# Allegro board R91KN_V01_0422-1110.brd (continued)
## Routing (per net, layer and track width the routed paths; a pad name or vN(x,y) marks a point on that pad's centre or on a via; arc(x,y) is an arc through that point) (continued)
M_MDA4: length 64.3
  TOP w0.099: U1.G29 97.72,49.4 97.48,49.65 97.48,49.8 97.6,49.92 97.78,49.92 97.9,49.8 98.03,49.8 98.15,49.67 98.15,49.33 97.91,49.09 97.91,48.89 98.06,48.73 98.06,48.45 98.04,48.42 98.04,47.94 98.05,47.92 98.07,47.9
  TOP w0.12: 98.07,47.9 98.2,47.77 98.2,47.09 98.97,46.32 98.97,45.78 99.52,45.24 v1(99.52,45.23) ; U202.F7 134.16,41.03 134.03,41.16 133.87,41.16 133.72,41.02 133.72,40.67 133.51,40.46 133.43,40.46 133.39,40.42 133.27,40.42 132.94,40.09 132.94,39.89 132.62,39.57 131.1,39.57 130.78,39.26 130.12,39.26 129.79,39.59 127.69,39.59 126.75,40.53 126.54,40.53 126.44,40.63 126.44,40.95 126.56,41.06 126.6,41.06 126.72,41.19 126.72,41.4 126.5,41.62 126.5,41.88 126.79,42.17 126.79,42.38 126.67,42.5 126.55,42.5 126.43,42.62 126.43,42.77 125.74,43.46 125.57,43.46 125.06,42.96 124.89,42.96 124.73,43.12 124.73,43.3 125.23,43.8 125.23,43.97 124.95,44.25 112.16,44.25 111.71,44.7 108.94,47.47 v1(108.79,47.47)
  BOTTOM w0.12: v1(108.79,47.47) 108.79,41.54 107.97,40.73 107.18,40.73 107.06,40.6 107.06,39.76 106.94,39.64 v4(106.82,39.64) 106.7,39.64 106.58,39.76 106.58,40.6 106.46,40.73 106.22,40.73 106.1,40.6 106.1,39.55 105.97,39.42 105.74,39.42 105.62,39.55 105.62,40.6 105.5,40.73 105.26,40.73 105.14,40.6 105.14,39.76 105.02,39.64 104.78,39.64 104.55,39.88 104.55,40.6 104.44,40.71 103.71,40.71 103.64,40.79 102.19,42.25 102.19,43.45 101.44,44.2 100.55,44.2 v1(99.52,45.23)
M_MDA5: length 64.1
  TOP w0.099: 98.23,48.95 98.23,48.85 98.27,48.81 98.29,48.81 98.42,48.69 98.42,48.69 98.42,48.55 98.25,48.37
  TOP w0.1: U1.F28 98.55,49.64 98.53,49.62 98.53,49.43 98.23,49.13 98.23,48.95 ; 98.42,47.88 98.23,48.07 98.23,48.34 98.25,48.35 98.25,48.37
  TOP w0.12: 98.42,47.88 98.42,47.88 98.42,47.35 99.55,46.23 99.57,46.23 100.16,45.65 v1(100.16,45.2) ; 133.37,40.81 133.29,40.88 133.06,40.88 132.93,40.76 132.93,40.59 132.81,40.46 131.23,40.46 130.91,40.78 129.96,40.78 129.81,40.64 127.4,40.64 127.2,40.84 127.2,42.55 125.11,44.64 112.32,44.64 109.03,47.93 v1(108.16,47.93)
  BOTTOM w0.12: v1(108.16,47.93) 108.38,47.71 108.38,41.68 108.1,41.4 107.86,41.4 107.73,41.52 v4(107.73,42.12) 107.73,42.49 107.61,42.62 107.27,42.62 107.14,42.49 107.14,41.31 107.14,41.3 107.02,41.19 106.78,41.19 106.66,41.31 106.66,42.49 106.53,42.62 106.31,42.62 106.18,42.49 106.18,41.31 106.18,41.3 106.06,41.19 105.82,41.19 105.7,41.31 105.7,42.49 105.57,42.62 105.34,42.62 105.22,42.49 105.22,41.31 105.22,41.3 105.1,41.19 104.86,41.19 104.74,41.31 104.74,42.49 104.62,42.62 104.38,42.62 104.26,42.5 104.26,41.31 104.14,41.19 103.85,41.19 103.72,41.31 103.72,42.48 103.6,42.61 103.38,42.61 103.25,42.48 103.25,42.17 103.12,42.05 102.94,42.05 102.62,42.36 102.62,43.7 102.09,44.24 101.7,44.24 101.34,44.6 100.68,44.6 100.21,45.07 100.21,45.15 v1(100.16,45.2)
M_MDA6: length 63.5
  TOP w0.1: U1.F32 98.57,48.2
  TOP w0.12: 133.37,42.41 133.01,42.06 131.51,42.06 131.26,42.3 131.26,42.32 130.4,43.19 127.67,43.19 125.43,45.44 112.64,45.44 109.32,48.75 106.1,48.75 106.05,48.69 v1(105.91,48.69) ; v1(100.76,45.65) 100.75,45.66 100.75,45.66 100.72,45.69 100.58,45.69 98.72,47.55 98.72,48.05 98.57,48.2
  BOTTOM w0.12: v1(105.91,48.69) 105.91,48.25 105.7,48.05 105.15,48.05 105.02,48.17 105.02,48.5 104.89,48.62 104.4,48.62 104.28,48.5 104.28,48.17 104.14,48.05 102.42,48.05 102.3,47.92 102.3,47.7 102.42,47.58 105.62,47.58 105.74,47.45 105.74,47.23 105.62,47.1 102.44,47.1 102.32,46.98 102.32,46.74 102.44,46.62 105.72,46.62 105.84,46.49 105.84,46.27 105.72,46.14 102.63,46.14 102.51,46.02 102.51,45.81 102.63,45.69 105.68,45.69 105.81,45.56 v4(105.81,45.3) 105.81,45.18 105.68,45.05 102.62,45.05 102.52,44.95 102.17,44.95 101.66,45.46 100.99,45.46 100.8,45.65 v1(100.76,45.65)
M_MDA7: length 63.8
  TOP w0.099: 98.92,48.59 98.55,48.96 U1.F30
  TOP w0.12: v1(106.44,48.34) 109.18,48.34 112.48,45.04 125.27,45.04 127.51,42.8 130.23,42.8 130.87,42.16 130.87,42.14 131.78,41.23 133.48,41.23 133.72,41.47 133.72,41.97 U202.H7 ; v1(101.53,45.02) 101.53,45.02 101.53,45.03 101.69,45.2 101.69,45.51 101.14,46.06 100.53,46.06 100.53,46.06 100.52,46.06 99.05,47.53 99.05,48.03 98.92,48.16 98.92,48.59
  BOTTOM w0.12: v1(106.44,48.34) 106.22,48.11 106.22,46.05 106.52,45.74 107.82,45.74 107.92,45.64 107.92,45.33 107.8,45.2 106.72,45.2 106.6,45.08 106.6,44.84 106.72,44.72 107.84,44.72 107.92,44.64 107.92,44.34 107.82,44.24 106.72,44.24 106.72,44.24 106.6,44.12 106.6,43.88 106.72,43.76 107.27,43.76 107.39,43.63 v4(107.39,43.4) 107.39,43.25 107.27,43.12 106.16,43.12 106.04,43.24 106.04,44.45 106.04,44.45 105.9,44.59 105.66,44.59 105.54,44.47 105.54,43.2 105.41,43.06 105.19,43.06 105.06,43.2 105.06,44.47 104.94,44.59 104.7,44.59 104.58,44.47 104.58,43.18 104.46,43.06 104.46,43.06 104.22,43.06 104.1,43.18 104.1,44.47 103.97,44.59 103.75,44.59 103.62,44.47 103.62,43.2 103.49,43.07 103.22,43.07 103.1,43.19 103.1,44.45 102.97,44.58 101.97,44.58 v1(101.53,45.02)
M_MDA8: length 66.2
  TOP w0.099: 101.58,48.28 101.41,48.28 101.07,48.62 100.93,48.62 100.92,48.63 100.8,48.63 100.58,48.84 100.58,49.05 100.45,49.17 100.28,49.17 100.15,49.05 U1.C30
  TOP w0.12: U202.A2 138.55,36.43 138.55,36.26 138.76,36.05 138.76,35.7 138.53,35.47 138.52,35.47 138.29,35.23 137.63,35.23 134.61,32.22 124.7,32.22 122.98,33.94 108.4,33.94 107.1,35.24 106.71,35.24 103.38,38.58 103.38,39.22 103.47,39.32 103.69,39.32 103.79,39.22 103.79,38.82 103.91,38.7 105.98,38.7 106.1,38.82 106.1,40.76 105.98,40.88 105.77,40.88 105.77,40.89 105.64,40.76 105.64,39.23 105.52,39.1 105.29,39.1 105.16,39.23 105.16,40.76 105.17,40.77 105.05,40.89 104.84,40.89 104.69,40.73 104.69,39.23 104.56,39.1 104.33,39.1 104.21,39.22 104.21,40.45 v4(104.09,40.57) 103.65,40.57 103.53,40.7 103.53,40.85 103.63,40.96 103.63,41.14 103.46,41.32 103.46,45.87 102.01,47.31 102.01,47.85 101.59,48.28 101.58,48.28
M_MDA9: length 67.3
  TOP w0.12: U202.C2 138.1,38.41 137.98,38.29 137.98,38.09 138.1,37.97 138.31,37.97 138.52,37.76 138.52,37.56 138.82,37.26 139.02,37.26 139.41,36.87 139.41,36.63 139.53,36.5 139.55,36.5 139.68,36.38 139.68,36.06 139.16,35.55 139.16,35.55 138.69,35.07 138.68,35.07 138.45,34.84 137.79,34.84 134.78,31.83 124.54,31.83 122.82,33.55 108.24,33.55 106.94,34.85 106.55,34.85 102.94,38.46 102.94,39.17 102.81,39.3 102.67,39.3 102.48,39.11 102.29,39.11 102.03,39.37 102.03,39.48 v4(102.14,39.59) 102.27,39.72 103.59,39.72 103.7,39.83 103.7,40.01 103.54,40.17 101.98,40.17 101.86,40.3 101.86,40.51 101.98,40.63 102.94,40.63 103.06,40.76 103.06,40.94 102.94,41.06 101.97,41.06 101.86,41.17 101.86,41.37 101.97,41.48 102.71,41.48 103.07,41.84 103.07,42.36 103.07,42.36 103.07,42.4 102.95,42.51 102.95,42.98 103.07,43.1 103.07,43.4 102.89,43.58 102.89,43.81 103.07,43.99 103.07,45.85 101.6,47.32 101.03,47.32 100.92,47.43 100.92,47.68 100.53,48.07 100.53,48.35 100.3,48.59 99.9,48.59 99.69,48.8 99.69,49.11 99.67,49.13 99.48,49.33 99.22,49.33 99.08,49.19 98.9,49.19 98.74,49.35 98.74,49.53 98.88,49.66 98.88,49.94 98.56,50.25 98.56,50.37 98.55,50.38 U1.F27
M_MDA10: length 66.1
  TOP w0.12: 137.37,36.81 137.21,36.81 137.02,36.63 137.02,36.29 137.18,36.14 137.18,35.89 134.29,33 125.03,33 123.3,34.73 115.2,34.73 114.7,35.24 114.7,36.05 114.82,36.18 114.82,38.38 114.56,38.64 114.56,38.91 113.02,40.46 110.59,40.46 109.75,41.3 108.75,41.3 107.45,40 107.45,39.05 107.65,38.85 108.5,38.85 108.67,38.67 108.67,38.48 108.55,38.35 107.55,38.35 107.45,38.25 107.45,38 107.55,37.9 108.5,37.9 108.6,37.8 108.6,37.55 108.45,37.4 107.6,37.4 107.5,37.3 107.5,37.05 107.65,36.9 108.35,36.9 108.5,36.75 108.5,36.5 108.3,36.3 107.5,36.3 107.23,36.02 107.04,36.02 106.9,36.16 v4(106.9,36.78) 106.9,40.33 106.9,41.32 106.66,41.55 106.66,41.55 106.54,41.68 104.4,41.68 104.24,41.83 104.24,46.38 103.98,46.64 103.98,46.97 102.92,48.03 102.92,48.23 101.35,49.8 U1.A28
M_MDA11: length 66.4
  TOP w0.12: 137.37,38.41 137.44,38.49 137.59,38.49 137.72,38.37 137.72,35.88 134.45,32.61 124.86,32.61 123.14,34.34 114.42,34.34 114.3,34.46 114.3,35.12 114.17,35.25 113.94,35.25 113.82,35.12 113.82,34.46 113.7,34.34 109.84,34.34 109.72,34.47 109.72,35.1 109.56,35.27 109.34,35.27 109.22,35.15 109.22,34.46 109.1,34.34 108.78,34.34 108.66,34.46 v4(108.66,34.62) 108.66,34.75 108.53,34.88 108.04,34.88 107.91,35 107.91,35.25 108.04,35.38 108.71,35.38 108.95,35.62 108.95,35.99 108.82,36.12 108.69,36.12 108.47,35.9 107.7,35.9 107.44,35.63 106.88,35.63 106.03,36.48 106.03,36.74 105.91,36.87 105.64,36.87 105.45,37.05 105.45,37.22 105.58,37.35 106.35,37.35 106.51,37.5 106.51,37.71 106.39,37.83 104.68,37.83 104.55,37.96 104.55,38.17 104.67,38.3 106.14,38.3 106.15,38.31 106.39,38.31 106.5,38.42 106.5,41.16 106.38,41.28 104.05,41.28 103.85,41.48 103.85,45.87 103.14,46.58 103.14,46.98 102.58,47.54 102.58,48.25 101.36,49.47 100.48,49.47 U1.C28
M_MDA12: length 67
  TOP w0.099: 101.33,50.68 101.09,50.92 100.81,50.92 100.78,50.88 100.56,50.88
  TOP w0.1: 100.56,50.88 100.32,50.88 100.28,50.92 100.02,50.92 99.95,50.86 99.41,50.86 99.31,50.76 99.31,50.64 U1.E27
  TOP w0.12: U202.A7 134.07,36.81 133.1,35.85 131.85,35.85 131.72,35.98 131.72,36.36 131.6,36.48 131.17,36.48 131.04,36.36 131.04,35.97 130.92,35.84 130.25,35.84 130.25,35.85 126.38,35.85 126.28,35.95 126.28,35.95 124.61,37.61 117.39,37.61 117.38,37.62 116.95,37.62 116.85,37.71 116.85,38.96 116.87,38.97 116.87,39.46 116.97,39.56 119.97,39.56 120.06,39.66 120.06,39.94 119.97,40.04 117.45,40.04 117.33,40.16 117.33,40.4 117.45,40.52 120,40.52 120.1,40.62 120.1,40.9 120,41 116.97,41 116.87,41.1 116.87,41.38 116.97,41.48 120.03,41.48 120.12,41.56 120.12,41.84 120.03,41.92 111.66,41.92 111.56,42.02 111.56,42.63 111.5,42.69 109.75,44.44 109.61,44.44 109.55,44.38 109.21,44.38 109.06,44.53 109.06,44.66 109.22,44.82 109.22,44.97 109.02,45.17 108.76,45.17 108.34,44.75 108.16,44.75 108,44.91 108,45.09 108.43,45.51 108.42,45.52 108.42,45.69 108.32,45.79 107.69,45.79 107.59,45.69 107.59,44.88 107.59,44.88 107.47,44.76 107.23,44.76 107.1,44.88 107.1,45.47 106.99,45.58 v4(106.96,45.58) 106.84,45.7 106.66,45.7 101.68,50.68 101.33,50.68
M_MDA13: length 67.9
  TOP w0.099: U1.G26 97.75,51.76 97.85,51.86 98.19,51.86 ; 98.67,51.08 98.87,51.27 98.87,51.53 ; 101.41,51.05 101.22,51.1 101.19,51.12 100.73,51.12 100.69,51.09 100.42,51.09 100.37,51.14
  TOP w0.1: 98.87,51.53 98.54,51.86 98.19,51.86 ; 100.37,51.14 99.98,51.14 99.97,51.12 99.93,51.12 99.87,51.06 99.32,51.06 99.01,50.74 98.87,50.74 98.67,50.94 98.67,51.08
  TOP w0.12: 102.98,49.8 106.53,46.24 108.5,46.24 112.4,42.34 112.41,42.34 112.42,42.34 120.41,42.34 120.52,42.24 120.52,39.48 120.2,39.17 117.36,39.17 117.26,39.06 117.26,38.81 117.25,38.8 117.25,38.1 117.34,38.01 117.59,38.01 117.71,38.13 117.71,38.66 117.83,38.78 118.07,38.78 118.19,38.66 118.19,38.13 118.31,38.01 118.55,38.01 118.67,38.13 118.67,38.66 118.79,38.78 119.03,38.78 119.15,38.66 119.15,38.13 119.27,38.01 119.51,38.01 119.63,38.13 119.63,38.66 119.75,38.78 119.99,38.78 120.11,38.66 120.11,38.13 120.23,38.01 120.47,38.01 120.59,38.13 120.59,38.95 120.69,39.05 120.97,39.05 121.02,38.99 121.02,38.99 121.07,38.95 121.07,38.13 121.19,38.01 121.46,38.01 121.56,38.11 121.56,39.25 121.69,39.38 121.93,39.38 122.05,39.26 122.05,39.22 122.05,38.11 122.15,38.01 122.43,38.01 122.53,38.11 122.53,39.22 122.53,39.26 122.65,39.38 122.89,39.38 123.01,39.26 123.01,39.22 123.01,38.1 123.11,38.01 123.43,38.01 123.53,38.1 123.53,39.28 123.63,39.38 123.97,39.38 124.11,39.24 v4(124.11,38.77) 124.11,38.08 124.16,38.02 124.69,38.02 124.77,38.09 124.77,39.17 124.88,39.29 125.12,39.29 125.22,39.19 125.22,37.68 125.32,37.58 131.28,37.58 131.38,37.48 131.38,37.33 131.53,37.18 133.26,37.18 133.35,37.27 133.35,37.38 133.37,37.4 133.37,37.62 ; 101.41,51.05 101.53,50.94 101.63,50.94
  TOP w0.13: 101.63,50.94 101.84,50.94 102.98,49.8
M_MDA14: length 67.1
  TOP w0.099: 102.16,51.55 101.92,51.79 101.47,51.79 101.37,51.7 101.36,51.69 100.73,51.69 100.71,51.71 100.42,51.71 100.39,51.69 99.85,51.69 99.75,51.59 U1.D26
  TOP w0.12: 133.37,38.41 133.37,38.52 133.26,38.62 133.02,38.62 132.92,38.52 132.92,38.27 132.91,38.27 132.91,38.09 132.79,37.97 132.41,37.97 132.21,37.77 132.21,37.5 132.1,37.4 131.78,37.4 131.68,37.5 131.68,37.57 131.44,37.8 131.44,37.8 131.28,37.98 125.73,37.98 125.63,38.08 125.63,42.06 125.53,42.16 125.32,42.16 125.22,42.06 125.22,39.77 125.13,39.69 124.86,39.69 124.77,39.77 124.77,42.03 124.65,42.15 124.41,42.15 124.29,42.03 124.29,39.87 124.21,39.78 123.9,39.78 123.81,39.87 123.81,42.03 123.69,42.15 123.45,42.15 123.33,42.03 123.33,39.9 123.21,39.77 122.94,39.77 122.85,39.87 122.85,42.03 122.73,42.15 122.49,42.15 122.37,42.03 122.37,39.9 122.25,39.77 121.97,39.77 121.89,39.85 121.89,42.03 121.77,42.15 121.53,42.15 121.41,42.03 121.41,39.8 121.27,39.66 v4(121.09,39.66) 121.05,39.66 120.92,39.78 120.92,42.15 121,42.23 121,42.63 120.89,42.74 112.56,42.74 111.85,43.45 111.84,43.45 108.66,46.65 106.75,46.65 106.74,46.65 106.6,46.65 106.31,46.94 106.31,47.22 106.09,47.44 105.8,47.44 102.16,51.08 102.16,51.55
M_MDA15: length 67.8
  TOP w0.099: U1.F25 98.55,52.39 98.65,52.49 98.94,52.49 99.03,52.39 99.03,51.65 99.22,51.46 99.37,51.46 99.47,51.56 99.47,51.78 99.57,51.88 100.31,51.88 100.34,51.91 100.79,51.91 100.82,51.89 101.1,51.89 101.13,51.91 101.34,51.97 101.35,51.97 101.37,51.99 102.14,51.99 102.55,51.58
  TOP w0.12: 102.55,51.58 102.55,51.01 105.23,48.33 105.62,48.33 105.7,48.24 105.7,47.96 105.81,47.85 106.53,47.85 106.63,47.75 106.63,47.58 106.67,47.54 106.67,47.19 106.78,47.09 107.43,47.09 107.45,47.06 107.8,47.06 107.82,47.09 108.59,47.09 108.62,47.06 108.75,47.06 108.77,47.04 108.81,47.04 112,43.85 112.5,43.85 112.6,43.74 v4(112.6,43.56) 112.6,43.33 112.79,43.13 113.12,43.13 113.24,43.25 113.24,43.79 113.31,43.85 113.58,43.85 113.7,43.74 113.7,43.23 113.8,43.13 114.08,43.13 114.18,43.23 114.18,43.74 114.3,43.85 114.54,43.85 114.66,43.74 114.66,43.23 114.76,43.13 115.04,43.13 115.14,43.23 115.14,43.74 115.26,43.85 115.5,43.85 115.62,43.74 115.62,43.23 115.72,43.13 116,43.13 116.1,43.23 116.1,43.76 116.2,43.85 116.5,43.85 116.6,43.76 116.6,43.23 116.7,43.13 116.98,43.13 117.08,43.23 117.08,43.76 117.18,43.85 117.46,43.85 117.56,43.76 117.56,43.23 117.66,43.13 117.94,43.13 118.04,43.23 118.04,43.76 118.14,43.85 118.41,43.85 118.5,43.76 118.5,43.23 118.6,43.13 118.91,43.13 119.01,43.23 119.01,43.72 119.11,43.81 119.43,43.81 119.53,43.72 119.53,43.23 119.63,43.13 119.92,43.13 120.03,43.23 120.03,43.76 120.12,43.85 120.37,43.85 120.47,43.76 120.47,43.23 120.57,43.13 120.84,43.13 120.92,43.21 120.92,43.71 121.02,43.81 121.3,43.81 121.4,43.71 121.4,42.65 121.5,42.55 121.74,42.55 121.84,42.65 121.84,43.7 121.96,43.81 122.2,43.81 122.32,43.7 122.32,42.65 122.42,42.55 122.7,42.55 122.8,42.65 122.8,43.7 122.92,43.81 123.16,43.81 123.28,43.7 123.28,42.65 123.38,42.55 123.66,42.55 123.76,42.65 123.76,43.71 123.86,43.81 124.14,43.81 124.24,43.72 124.24,43.71 124.24,42.64 124.33,42.55 125.93,42.55 126.05,42.44 126.05,40.24 126.15,40.14 126.59,40.14 126.82,39.9 126.82,39.77 126.72,39.67 126.15,39.67 126.05,39.57 126.05,39.3 126.15,39.2 127.06,39.2 127.16,39.1 127.16,38.88 127.06,38.77 126.15,38.77 126.05,38.67 126.05,38.47 126.15,38.37 131.59,38.37 131.69,38.47 131.69,38.54 131.75,38.61 131.75,38.63 131.91,38.78 132.16,38.78 132.26,38.88 132.4,38.88 132.42,38.86 132.71,38.86 132.83,38.98 133.07,38.98 133.19,38.87 133.22,38.87 133.22,38.86 133.51,38.86 133.63,38.98 134.06,38.98 134.16,39.08 134.16,39.22
M_MDA16: length 65.3
  TOP w0.099: U1.A25 101.31,52.2 101.32,52.19 102.23,52.19 102.38,52.03 102.62,51.79 102.64,51.79 102.73,51.7 102.98,51.03 104.16,50.04 104.18,50.04
  TOP w0.12: 104.18,50.04 104.18,50.03 105.91,50.03 106.22,49.72 v1(106.22,49.69)
  BOTTOM w0.12: v1(106.22,49.69) 106.72,48.77 107,48.5 108.05,48.5 108.26,48.34 108.37,48.28 108.96,47.88 109.2,47.64 109.2,42.12 110.78,40.53 112.11,40.53 112.64,40.52 115.31,38.64 124.09,29.86 v4(124.69,29.86) 135.69,29.86 141.7,35.87 141.7,40.58 140.56,42.2 140.3,42.62 140.3,42.63 140.06,42.87 139.09,42.87 139.06,42.84 138.87,42.79 U201.H8
M_MDA17: length 65.8
  TOP w0.099: 103.34,51.26 103.34,51.37 102.32,52.39 101.4,52.39 101.36,52.44 101.25,52.47 101.22,52.47 101.14,52.49 101.12,52.51 100.82,52.51 100.74,52.48 100.52,52.26 100.29,52.26 U1.C25
  TOP w0.12: v1(106.81,50.29) 106.78,50.29 106.77,50.3 104.29,50.3 104.06,50.53 104.06,50.54 103.34,51.26
  BOTTOM w0.12: 137.37,42.41 137.75,42.03 139.73,42.03 141.31,40.45 141.31,36.03 135.53,30.25 125.62,30.25 124.83,31.05 v4(124.05,31.05) 123.46,31.05 115.28,39.23 114.86,39.43 112.77,40.9 111.61,40.95 110.92,40.95 109.59,42.27 109.59,47.83 108.85,48.57 108.85,49.18 107.53,50.51 106.93,50.51 106.81,50.38 v1(106.81,50.29)
M_MDA18: length 66
  TOP w0.099: 104.01,51.15 102.56,52.6 101.48,52.6 101.37,52.71 100.71,52.71 100.68,52.69 99.94,52.69 99.81,52.56 99.81,52.33 99.69,52.2 U1.E25
  TOP w0.12: v1(108.22,50.41) 108.22,50.24 108.1,50.12 107.34,50.12 107.22,50.24 107.22,50.46 106.97,50.7 104.45,50.7 104.22,50.93 104.22,50.93 104.01,51.15
  BOTTOM w0.12: v1(108.22,50.41) 108.43,50.41 108.56,50.28 108.56,50.24 108.62,50.17 108.62,49.96 109.05,49.54 109.13,49.54 109.26,49.41 109.26,49.15 109.38,49.02 109.43,49.02 109.56,48.9 109.56,48.42 109.99,47.98 109.99,47.86 110.05,47.8 110.05,43.06 110.05,43.05 110.05,42.38 111.07,41.36 111.75,41.36 111.75,41.35 112.07,41.35 112.07,41.36 112.1,41.36 112.52,41.32 112.88,41.29 112.97,41.24 114.49,40.17 115.07,39.77 115.51,39.55 122.92,32.15 v4(123.32,32.15) 124.49,32.15 125.99,30.65 135.37,30.65 140.92,36.2 140.92,40.24 140.38,40.78 140.38,40.78 140.13,41.02 140.13,41.02 139.91,41.24 139.76,41.24 139.69,41.17 139.35,41.17 139.27,41.26 138.82,41.26 138.78,41.3 138.35,41.3 138.31,41.26 138.02,41.26 137.93,41.35 137.6,41.35 137.31,41.06 137.31,40.87 137.37,40.81
M_MDA19: length 66.2
  TOP w0.1: 102.69,53.01 102.2,53.01 101.82,53.4 101.48,53.4 101.37,53.28 100.72,53.28 100.68,53.31 99.85,53.31 99.72,53.19 99.72,53.02 U1.D24
  TOP w0.12: v1(108.97,50.41) 108.97,50.45 108.31,51.09 107.98,51.09 107.86,50.97 107.86,50.82 107.73,50.7 107.53,50.7 107.13,51.09 104.6,51.09 102.69,53.01
  BOTTOM w0.12: U201.F8 137.88,40.81 137.75,40.69 137.75,40.49 137.88,40.37 139.11,40.37 139.32,40.15 139.32,39.6 139.59,39.34 140.4,39.34 140.53,39.21 140.53,38.8 140.41,38.68 140.07,38.68 139.95,38.56 139.95,38.32 140.07,38.2 140.41,38.2 140.53,38.08 140.53,36.36 135.21,31.04 126.15,31.04 124.42,32.77 122.84,32.77 115.74,39.87 115.27,40.11 115.18,40.17 115.08,40.24 114.59,40.59 113.17,41.58 112.99,41.67 112.1,41.75 111.3,41.75 111.17,41.88 v4(111.17,42.15) 111.17,42.41 111.05,42.53 110.57,42.53 110.44,42.66 110.44,43.22 110.44,43.22 110.44,48.16 110.16,48.44 110.16,48.47 109.98,48.64 109.98,49.44 109.89,49.53 109.7,49.53 109.55,49.68 109.55,49.9 109.67,50.02 109.94,50.02 110.03,50.12 110.03,50.4 109.91,50.52 109.07,50.52 v1(108.97,50.41)
M_MDA20: length 66.5
  TOP w0.099: U1.E23 99,53.8 98.81,53.98 98.81,54.11 98.91,54.2 99.31,54.2 99.36,54.24 99.85,54.24 99.93,54.32 100.39,54.32 100.43,54.29 100.68,54.29 100.72,54.32 101.36,54.32 101.48,54.2 101.95,54.2 101.95,54.2 102.16,54.38 103.56,54.38
  TOP w0.12: 103.56,54.38 104.97,52.96 109.08,52.96 110.86,51.17 110.86,50.39 112.96,48.29 113.82,48.29 114.66,47.45 114.66,47.28 114.73,47.22 114.73,46.7 114.9,46.53 114.9,46.34 115.03,46.22 119.72,46.22 119.84,46.34 119.84,47.57 119.96,47.69 120.2,47.69 120.32,47.57 120.32,46.34 120.44,46.22 120.6,46.22 120.72,46.34 120.72,47.52 120.85,47.65 121.08,47.65 121.21,47.52 121.21,46.32 121.31,46.22 121.58,46.22 121.68,46.33 121.68,47.04 121.78,47.14 122.02,47.14 122.02,47.14 122.16,47 122.16,46.34 122.28,46.22 122.52,46.22 122.64,46.34 122.64,47.04 122.74,47.14 122.98,47.14 122.98,47.14 123.12,47 123.12,46.34 123.24,46.22 123.48,46.22 123.6,46.34 123.6,47.04 123.7,47.14 123.94,47.14 123.94,47.14 124.08,47 124.08,46.34 124.2,46.22 124.44,46.22 124.56,46.34 124.56,47.04 124.66,47.14 124.9,47.14 124.9,47.14 125.04,47 125.04,46.33 125.15,46.22 125.41,46.22 125.51,46.33 125.51,46.63 125.63,46.74 125.79,46.74 125.9,46.63 125.9,46.08 126.22,45.76 126.51,45.76 126.75,45.99 126.75,46.13 126.62,46.26 126.47,46.26 126.34,46.38 126.34,46.52 126.47,46.65 126.62,46.65 126.75,46.77 126.75,47.09 126.62,47.21 126.4,47.21 126.22,47.03 126.06,47.03 125.83,47.27 125.56,47.27 125.38,47.44 v1(125.38,47.53)
  BOTTOM w0.12: 133.37,41.62 133.07,41.62 132.69,41.23 131.79,41.23 131.56,41.48 131.56,41.54 131.43,41.66 131.33,41.66 130.85,42.14 130.69,42.14 130.56,42.02 130.56,41.84 130.44,41.72 129.9,41.72 129.82,41.64 127.49,41.64 125.93,43.2 125.93,45.84 126,45.91 126,45.95 126.41,46.37 126.41,46.38 126.66,46.62 126.66,47.27 126.53,47.4 126.25,47.4 126.25,47.4 126.03,47.4 125.91,47.52 125.91,47.65 126.03,47.77 126.19,47.77 126.29,47.88 126.29,48.1 126.19,48.2 125.12,48.2 125.01,48.1 125.01,47.8 125.29,47.53 v1(125.38,47.53)
M_MDA21: length 66.9
  TOP w0.099: 102.17,54.1 102.07,54 101.4,54 101.34,54.06 101.15,54.12 100.81,54.12 100.78,54.09 100.32,54.09 100.29,54.12 100.02,54.12 99.82,53.93 99.82,53.83
  TOP w0.1: U1.F23 98.87,53.48 99.48,53.48 99.82,53.83
  TOP w0.12: 102.17,54.1 103.52,54.1 105.06,52.56 108.92,52.56 110.47,51.01 110.47,50.23 113.06,47.64 113.8,47.64 113.81,47.63 v1(113.88,47.63)
  BOTTOM w0.12: U201.E3 134.48,40.02 134.5,40.01 134.8,40.01 134.91,39.89 134.91,39.5 134.79,39.38 134.68,39.38 134.56,39.25 134.56,38.75 134.63,38.67 134.75,38.67 134.85,38.58 134.85,36.45 134.43,36.02 134.42,36.02 133.46,35.06 128.13,35.06 v4(127.99,35.2) 127.66,35.2 127.47,35.39 127.47,35.53 127.63,35.7 127.63,35.83 127.51,35.95 127.38,35.95 127.29,35.86 127,35.86 126.87,35.99 126.87,36.14 127.01,36.28 127.01,36.45 125.42,38.04 125.25,38.04 125.12,37.91 124.95,37.91 124.78,38.08 124.78,38.25 124.91,38.38 124.91,38.55 124.74,38.72 124.57,38.72 124.44,38.59 124.27,38.59 124.1,38.76 124.1,38.93 124.23,39.06 124.23,39.23 124.06,39.4 123.89,39.4 123.76,39.27 123.6,39.27 123.43,39.44 123.43,39.61 123.55,39.74 123.55,39.91 123.38,40.08 123.21,40.08 123.09,39.95 122.92,39.95 122.75,40.12 122.75,40.29 122.88,40.42 122.88,40.59 122.71,40.76 122.54,40.76 122.41,40.63 122.24,40.63 122.07,40.8 122.07,40.97 122.2,41.1 122.2,41.27 122.03,41.44 121.86,41.44 121.73,41.31 121.56,41.31 121.39,41.48 121.39,41.65 121.52,41.78 121.52,41.95 121.35,42.12 121.18,42.12 121.05,41.99 120.88,41.99 120.71,42.16 120.71,42.33 120.84,42.46 120.84,42.63 120.67,42.8 120.5,42.8 120.37,42.67 120.2,42.67 120.03,42.84 120.03,43.01 120.16,43.14 120.16,43.31 119.99,43.48 119.82,43.48 119.69,43.35 119.52,43.35 119.35,43.52 119.35,43.69 119.48,43.81 119.48,43.98 119.19,44.27 119.19,44.59 119.19,44.6 119.19,47.94 119.07,48.06 118.87,48.06 118.75,47.94 118.75,47 118.62,46.87 118.39,46.87 118.27,47 118.27,47.94 118.27,47.95 118.15,48.06 117.94,48.06 117.81,47.95 117.81,47 117.69,46.87 117.46,46.87 117.34,47 117.34,47.94 117.34,47.95 117.34,47.95 117.22,48.06 117.05,48.06 116.92,47.94 116.92,46.99 116.8,46.87 116.6,46.87 116.47,46.99 116.47,47.94 116.35,48.06 116.18,48.06 116.06,47.94 116.06,47.02 115.93,46.9 115.77,46.9 115.64,47.02 115.64,47.59 115.58,47.66 115.57,47.66 115.23,47.66 115.23,47.66 113.9,47.66 v1(113.88,47.63)
M_MDA22: length 66.6
  TOP w0.099: 100.97,54.88 101.37,54.88 101.37,54.89 101.48,55 101.82,55 102.09,54.73
  TOP w0.1: U1.D22 100.03,54.88 100.39,54.88 100.42,54.91 100.68,54.91 100.71,54.88 100.97,54.88
  TOP w0.12: 102.09,54.73 103.68,54.73 105.05,53.35 109.24,53.35 111.26,51.33 111.26,50.56 113.13,48.69 114.16,48.69 114.53,48.32 114.53,48.31 114.75,48.09 114.88,48.09 114.88,48.08 115.08,48.08 115.18,47.98 115.18,47.97 115.18,46.8 115.32,46.66 115.54,46.66 115.66,46.79 115.66,47.94 115.8,48.08 116.02,48.08 116.15,47.95 116.15,46.74 116.27,46.62 116.5,46.62 116.63,46.74 116.63,47.95 116.75,48.08 116.94,48.08 117.07,47.95 117.07,46.74 117.19,46.62 117.42,46.62 117.55,46.74 117.55,47.95 117.67,48.08 117.99,48.08 118.12,47.95 118.12,46.74 118.24,46.62 118.43,46.62 118.56,46.74 118.56,47.95 118.68,48.08 118.88,48.08 119,47.95 119,46.78 119.12,46.66 119.32,46.66 119.44,46.78 119.44,47.95 119.57,48.08 119.78,48.08 119.8,48.09 120.37,48.09 120.38,48.08 121.78,48.08 121.79,48.07 124.53,48.07 125.03,48.56 125.03,48.75 125.15,48.88 125.37,48.88 125.49,48.75 125.49,48.53 125.61,48.41 125.77,48.41 125.88,48.53 125.88,48.75 126.01,48.88 126.18,48.88 126.31,48.75 126.31,48.34 126.18,48.22 126.09,48.22 125.81,47.94 125.22,47.94 124.97,47.7 124.97,47.68 124.85,47.55 v1(124.69,47.55)
  BOTTOM w0.12: v1(124.69,47.55) 124.5,47.55 124.27,47.33 124.27,47.13 124.4,47.01 125.98,47.01 126.11,46.88 126.11,46.62 126.02,46.53 124.35,46.53 124.23,46.41 124.23,46.16 124.39,46.01 124.57,46.01 v4(124.62,45.96) 124.66,46.01 125.44,46.01 125.54,45.91 125.54,45.68 125.41,45.55 125.03,45.55 124.91,45.43 124.91,45.23 124.94,45.21 124.94,45.07 125.03,44.97 125.41,44.97 125.54,44.84 125.54,43.04 127.1,41.48 127.1,41.16 127.62,40.64 129.81,40.64 129.96,40.78 130.31,40.78 131.03,40.06 131.84,40.06 132.15,40.37 132.62,40.37 133.07,40.81 133.37,40.81
M_MDA23: length 67.2
  TOP w0.099: 102.67,55.02 102.07,55.02 101.9,55.2 101.19,55.2 101.08,55.09 100.82,55.09 100.61,55.3 100.5,55.3
  TOP w0.1: U1.F21 98.4,55.25 98.4,55.23 98.34,55.17 98.34,55.04 98.47,54.91 98.77,54.91 98.88,55.02 98.88,55.04 99,55.16 99.13,55.16 99.22,55.09 99.26,55.09 99.44,54.9 99.6,54.9 99.62,54.91 99.78,54.91 99.94,55.09 100.28,55.09 100.5,55.3
  TOP w0.12: 102.67,55.02 103.94,55.02 105.21,53.75 109.39,53.75 111.65,51.5 111.65,50.72 113.29,49.08 114.32,49.08 114.92,48.48 122.88,48.48 123.13,48.73 123.13,48.81 123.51,49.19 123.86,49.19 123.98,49.31 123.98,49.52 123.86,49.65 123.52,49.65 123.43,49.74 123.43,50.02 123.53,50.12 123.58,50.12 123.84,50.38 124.22,50.38 124.22,50.38 124.57,50.38 124.68,50.28 125.38,50.28 125.49,50.17 125.49,49.95 125.73,49.72 125.86,49.72 125.98,49.59 125.98,49.41 125.75,49.18 125.62,49.18 125.53,49.27 124.99,49.27 124.9,49.18 124.41,49.18 124.16,48.93 124.16,48.67 124.03,48.55 123.93,48.55 v1(123.9,48.52)
  BOTTOM w0.12: U201.H3 134.16,42.1 134.04,41.98 134.01,41.98 133.8,41.77 133.8,41.47 133.97,41.3 133.97,41.13 133.8,40.97 133.8,40.74 133.43,40.37 133.22,40.37 132.92,40.07 132.92,39.87 132.62,39.57 132.23,39.57 131.91,39.26 130.05,39.26 129.72,39.59 127.72,39.59 127.21,40.09 127.21,40.49 126.71,41 126.71,41.19 125.16,42.74 125.16,42.77 124.89,43.04 124.89,43.32 125.15,43.58 125.15,44.44 125.02,44.56 124.85,44.56 124.63,44.34 124.5,44.34 124.35,44.48 124.35,44.69 124.54,44.87 124.54,45.05 124.34,45.24 124.16,45.24 123.97,45.05 123.8,45.05 123.63,45.22 123.63,45.39 123.83,45.59 123.83,45.76 123.76,45.83 123.76,46.38 v4(123.66,46.47) 123.37,46.77 123.37,46.94 123.58,47.15 123.58,47.32 123.41,47.49 123.24,47.49 123.03,47.28 122.86,47.28 122.67,47.47 122.33,47.47 122.1,47.7 122.1,47.93 122.23,48.05 123.25,48.05 123.38,48.18 123.38,48.38 123.25,48.51 122.1,48.51 121.98,48.63 121.98,48.83 122.1,48.95 123.43,48.95 123.55,49.08 123.55,49.62 123.68,49.74 124,49.74 124.13,49.62 124.13,48.65 124,48.52 v1(123.9,48.52)
M_MDA24: length 66.9
  TOP w0.099: 101.18,55.91 101.24,55.91 101.35,55.8
  TOP w0.1: 101.35,55.8 102.01,55.8 102.09,55.88 ; 101.18,55.91 101.18,55.91 101.1,55.91 101.09,55.92 100.71,55.92 100.67,55.88 100.1,55.88 99.53,55.31 99.44,55.31 U1.E21
  TOP w0.12: 102.09,55.88 104.83,55.88 105.73,54.97 109.84,54.97 112.83,51.98 112.83,51.26 v1(113.7,50.38)
  BOTTOM w0.12: v1(113.7,50.38) 110.8,50.38 110.43,50.08 110.45,49.61 110.56,48.63 110.56,48.6 110.83,48.32 110.83,43.39 112.07,42.15 113.1,42.05 113.37,41.92 113.98,41.49 114.81,40.91 115.31,40.56 115.97,40.2 120.97,35.2 123.23,33.16 124.58,33.16 126.31,31.43 135.05,31.43 140.13,36.52 140.13,37.58 139.89,37.82 139.37,37.83 139.33,37.87 139.14,37.93 138.94,37.99 U201.C8
M_MDA25: length 66.7
  TOP w0.099: 101.96,56.59 101.96,56.6 101.36,56.6 101.25,56.49 100.71,56.49 100.68,56.51 100.42,56.51 100.11,56.2 U1.D20
  TOP w0.1: 101.96,56.59 102.38,56.18 103.04,56.18
  TOP w0.12: 103.04,56.18 104.98,56.18 105.79,55.37 110,55.37 113.22,52.14 113.22,51.66 v1(114.47,50.41)
  BOTTOM w0.12: 138.16,37.62 138.16,37.86 138.29,37.98 138.48,37.98 138.61,37.86 138.61,36.2 138.76,36.05 138.76,35.71 134.88,31.82 126.48,31.82 124.75,33.55 123.38,33.55 121.24,35.48 116.42,40.3 116.21,40.51 115.62,40.83 115.5,40.9 115.49,40.92 114.16,41.84 113.57,42.25 113.21,42.44 112.76,42.48 112.19,42.59 111.23,43.55 111.23,48.48 110.95,48.76 110.95,48.99 111.07,49.12 111.92,49.12 112.05,49.24 v4(112.05,49.4) 111.92,49.52 110.97,49.52 110.84,49.65 110.84,49.85 110.97,49.98 114,49.98 114.43,50.41 v1(114.47,50.41)
M_MDA26: length 67.3
  TOP w0.099: 98.4,56.76 98.4,56.88 98.53,57 U1.F19 ; 100.63,56.87 100.8,56.7 ; 99.12,56.3 99.19,56.3 99.2,56.28 99.33,56.28 99.38,56.34 ; 99.93,56.47 100.06,56.47 100.27,56.67
  TOP w0.1: 100.8,56.7 100.81,56.69 101.09,56.69 101.2,56.8 102.14,56.8 102.49,56.45 ; 98.4,56.76 98.56,56.6 98.89,56.6 99.02,56.48 99.02,56.41 99.12,56.3 ; 100.63,56.87 100.47,56.87 100.28,56.67 100.27,56.67 ; 99.93,56.47 99.83,56.57 99.77,56.57 99.65,56.69 99.51,56.69 99.38,56.57 99.38,56.34
  TOP w0.12: v1(115.19,50.42) 115.38,50.42 115.5,50.55 115.5,50.77 115.4,50.87 114.72,50.87 114.58,51.02 v4(114.58,51.34) 114.36,51.56 114.19,51.56 114.12,51.49 113.95,51.49 113.78,51.66 113.78,51.83 113.85,51.89 113.85,52.06 110.16,55.76 105.81,55.76 105.12,56.45 102.49,56.45
  BOTTOM w0.12: 137.37,39.22 137.59,39.22 137.6,39.2 137.66,39.2 137.88,38.98 137.88,38.63 137.81,38.56 137.81,38.06 137.73,37.98 137.73,37.49 137.81,37.41 137.81,35.73 137.96,35.58 137.96,35.46 134.72,32.22 126.64,32.22 124.91,33.95 123.55,33.95 116.45,40.83 115.83,41.17 114.39,42.16 113.78,42.59 113.32,42.82 112.82,42.87 112.51,42.98 111.62,43.86 111.62,48.18 112.95,49.51 114.29,49.51 115.19,50.41 v1(115.19,50.42)
M_MDA27: length 66.3
  TOP w0.099: U1.A19 101.9,57
  TOP w0.1: 101.9,57 102.47,57 102.75,56.73
  TOP w0.12: 102.75,56.73 105.3,56.73 105.81,56.22 110.25,56.22 110.54,55.93 110.71,55.93 110.98,56.19 111.15,56.19 111.32,56.03 111.32,55.85 111.05,55.59 111.05,55.42 111.22,55.25 111.39,55.25 111.66,55.52 111.84,55.52 112,55.36 112,55.18 111.73,54.91 111.73,54.74 111.9,54.57 112.07,54.57 112.36,54.86 112.54,54.86 v4(112.7,54.7) 112.7,54.52 112.41,54.23 112.41,54.06 112.58,53.89 112.75,53.89 112.97,54.12 113.15,54.12 113.31,53.95 113.31,53.78 113.09,53.55 113.09,53.38 113.26,53.21 113.43,53.21 113.7,53.48 113.88,53.48 114.04,53.32 114.04,53.14 113.77,52.87 113.77,52.7 113.94,52.53 114.11,52.53 114.41,52.84 114.59,52.84 114.75,52.68 114.75,52.5 114.53,52.28 114.53,52.1 114.69,51.94 114.87,51.94 115.18,52.25 115.36,52.25 115.52,52.09 115.52,51.91 115.19,51.57 115.19,51.46 115.38,51.27 116,51.27 116.13,51.13 116.13,50.55 116,50.42 v1(115.91,50.42)
  BOTTOM w0.12: 137.37,36.81 137.29,36.74 137.29,35.45 137.28,35.43 137.28,35.43 134.47,32.62 134.47,32.62 134.46,32.61 126.8,32.61 125.06,34.34 123.71,34.34 123.68,34.37 116.68,41.15 116.03,41.5 114.61,42.48 113.98,42.93 113.42,43.21 112.96,43.25 112.02,44.19 112.02,48.02 113.12,49.12 114.62,49.12 115.91,50.41 v1(115.91,50.42)
M_MDA28: length 67
  TOP w0.099: 101.84,58.17 101.81,58.17 101.77,58.21 101.38,58.21 101.29,58.12 101.22,58.09 100.73,58.09 100.71,58.11 100.42,58.11 100.37,58.06 99.8,58.06 ; U1.D18 99.75,58.01
  TOP w0.1: 99.75,58.01 99.8,58.06 ; 101.84,58.17 101.88,58.13
  TOP w0.12: 105.67,57.67 105.67,57.68 112.73,57.68 113.38,57.03 113.55,57.03 114.02,57.51 114.19,57.51 114.36,57.34 114.36,57.17 113.88,56.69 113.88,56.52 114.05,56.35 114.22,56.35 114.7,56.83 114.87,56.83 115.04,56.66 115.04,56.49 114.56,56.01 114.56,55.85 114.73,55.68 114.9,55.68 115.38,56.15 115.55,56.15 115.72,55.98 115.72,55.81 115.24,55.34 115.24,55.17 115.41,55 115.58,55 116.06,55.47 116.23,55.47 116.4,55.3 116.4,55.13 115.92,54.66 115.92,54.49 116.09,54.32 116.26,54.32 116.74,54.79 116.91,54.79 117.08,54.62 117.08,54.45 116.6,53.98 116.6,53.81 116.77,53.64 116.94,53.64 117.42,54.11 117.59,54.11 117.76,53.94 117.76,53.77 117.28,53.3 117.28,53.13 117.45,52.96 117.62,52.96 118.1,53.44 118.26,53.44 118.43,53.27 118.43,53.1 117.96,52.62 117.96,52.45 118.08,52.33 118.08,52.12 117.75,51.8 117.75,51.67 117.92,51.5 117.92,51.48 118.32,51.09 118.32,50.51 118.2,50.38 v1(118.08,50.38)
  TOP w0.13: 101.88,58.13 102.33,57.67 105.67,57.67
  BOTTOM w0.12: v1(118.08,50.38) 117.6,49.91 117.6,49.35 v4(117.28,49.02) 116.99,48.73 116.99,48.56 117.09,48.46 117.89,48.46 118.02,48.58 118.02,49.15 118.14,49.27 118.41,49.27 118.54,49.15 118.54,48.58 118.66,48.46 118.94,48.46 119.06,48.58 119.06,49.06 119.19,49.19 119.46,49.19 119.59,49.06 119.59,44.44 128.57,35.45 133.29,35.45 134.3,36.46 134.3,36.46 134.31,36.46 134.52,36.67 134.52,38.06 U201.C3
M_MDA29: length 67.6
  TOP w0.099: 99.48,58.29 100.28,58.29 100.31,58.31 100.79,58.31 100.82,58.29 101.08,58.29 101.2,58.41 101.85,58.41 101.87,58.4 101.93,58.38 ; 98.84,59.03 98.67,59.03 98.55,58.91 U1.F17
  TOP w0.1: 99.48,58.29 99.35,58.16 99.35,57.94 99.24,57.83 99.07,57.83 98.95,57.94 98.95,58.91 98.84,59.03
  TOP w0.12: v1(120.54,50.4) 120.56,50.42 120.56,50.77 120.44,50.89 118.87,50.89 118.74,51.02 118.74,51.2 118.86,51.32 118.89,51.31 120.46,51.31 120.59,51.44 120.59,51.67 120.46,51.8 118.89,51.8 118.61,51.81 118.5,51.93 118.5,52.16 118.62,52.27 120.46,52.27 120.59,52.4 120.59,52.62 120.48,52.73 120.27,52.73 120.26,52.73 118.96,52.73 118.84,52.86 118.84,53.09 118.96,53.21 120.48,53.21 120.59,53.32 120.59,53.59 120.48,53.69 118.56,53.69 118.34,53.91 v4(118.34,54.06) 118.47,54.19 119.87,54.19 120,54.31 120,54.59 119.87,54.72 117.58,54.72 114.22,58.07 113.96,58.07 113.65,57.77 113.3,57.77 112.99,58.07 102.36,58.07 102.05,58.38 101.93,58.38
  BOTTOM w0.12: U201.A3 134.09,36.81 133.12,35.84 128.73,35.84 122.03,42.54 122.03,42.54 119.98,44.6 119.98,49.22 120.28,49.53 120.28,49.81 120.54,50.07 v1(120.54,50.4)
M_MDA30: length 66.4
  TOP w0.099: U1.A17 100.96,58.61 102.14,58.61
  TOP w0.12: v1(120.77,49.72) 120.98,49.93 120.98,54 120.85,54.12 120.51,54.12 120.39,54.24 120.39,54.41 120.52,54.53 120.84,54.53 120.96,54.66 120.96,55.26 120.77,55.45 120.53,55.45 120.41,55.33 120.41,55.26 v4(120.28,55.13) 119.82,55.13 119.7,55.26 119.7,56.35 119.57,56.48 119.34,56.48 119.22,56.35 119.22,55.26 119.1,55.13 118.86,55.13 118.74,55.26 118.74,56.2 118.61,56.32 118.38,56.32 118.26,56.2 118.26,55.26 118.14,55.13 117.71,55.13 117.21,55.64 117.21,55.81 118.04,56.64 118.04,56.82 117.88,56.98 117.7,56.98 116.87,56.15 116.7,56.15 116.53,56.32 116.53,56.49 117.42,57.38 117.42,57.55 117.26,57.71 117.08,57.71 116.19,56.83 116.02,56.83 115.85,57 115.85,57.17 116.79,58.1 116.79,58.28 116.62,58.44 116.45,58.44 115.51,57.51 115.34,57.51 115.17,57.68 115.17,57.85 115.49,58.17 115.49,58.34 115.37,58.47 115.11,58.47 114.83,58.19 114.66,58.19 114.39,58.46 102.62,58.46 102.61,58.47 102.29,58.47 102.14,58.61
  BOTTOM w0.12: v1(120.77,49.72) 120.67,49.62 120.67,49.37 120.67,49.36 120.67,49.09 120.38,48.79 120.38,44.76 128.71,36.42 128.84,36.42 128.96,36.55 128.96,37.06 129.08,37.19 129.34,37.19 129.47,37.06 129.47,36.37 129.59,36.24 129.82,36.24 129.95,36.37 129.95,36.56 130.07,36.69 130.71,36.69 130.83,36.56 130.83,36.37 130.96,36.24 131.76,36.24 131.89,36.37 131.89,36.44 132.21,36.76 132.21,36.96 132.42,37.17 132.5,37.17 132.59,37.26 132.71,37.26 132.75,37.3 133.18,37.3 133.35,37.12 133.35,37.05 133.37,37.03 133.37,36.81
M_MDA31: length 66.8
  TOP w0.099: U1.C17 100.5,58.6 100.82,58.91 101.08,58.91 101.16,58.83 102.43,58.83 102.45,58.86
  TOP w0.12: 102.45,58.86 117.09,58.86 117.22,58.98 117.22,59.12 118.05,59.94 119.71,59.94 119.84,59.81 119.84,59.53 119.71,59.41 118.07,59.41 117.95,59.28 117.95,59.1 118.07,58.98 119.58,58.98 119.7,58.85 119.7,58.63 119.58,58.51 117.55,58.51 117.42,58.38 v4(117.42,58.29) 117.42,58.12 117.78,57.77 118.17,57.77 118.4,58 120.09,58 120.21,57.88 120.21,57.59 120.09,57.47 118.42,57.47 118.3,57.34 118.3,57.11 118.64,56.77 119.05,56.77 119.27,56.99 120.09,56.99 120.21,56.87 120.21,55.97 120.34,55.84 120.93,55.84 121.37,55.4 121.37,50.32 121.45,50.24 v1(121.45,49.9)
  BOTTOM w0.12: v1(121.45,49.9) 121.18,49.63 121.18,48.97 120.77,48.56 120.77,44.92 127.42,38.27 127.88,38.27 128.29,37.86 128.29,37.42 128.42,37.3 128.63,37.3 128.77,37.43 128.77,37.86 128.89,37.98 129.13,37.98 129.25,37.86 129.25,37.68 129.35,37.58 129.61,37.58 129.73,37.7 129.73,37.86 129.85,37.98 130.09,37.98 130.21,37.86 130.21,37.7 130.33,37.58 130.57,37.58 130.69,37.7 130.69,37.86 130.81,37.98 131.15,37.98 131.54,37.59 132.03,37.59 132.41,37.97 133.24,37.97 133.35,38.08 133.35,38.19 133.37,38.2 133.37,38.41
M_MDA32: length 67.2
  TOP w0.099: 101.25,59.09 101.3,59.04 101.84,59.04 101.85,59.05 101.94,59.12 102.3,59.12 ; U1.E17 99.56,58.81 99.65,58.81
  TOP w0.1: 99.65,58.81 99.93,59.09 100.67,59.09 100.7,59.11 101.23,59.11 101.25,59.09
  TOP w0.12: 102.3,59.12 102.45,59.27 116.82,59.27 117.88,60.33 117.88,60.33 119.77,60.33 120.61,61.17 120.61,62.07 120.4,62.28 120.4,63 121.5,64.1 122.93,64.1 123.05,63.98 v1(123.05,63.83)
  BOTTOM w0.12: U402.D7 134.1,77.31 133.8,77.31 133.51,77.02 131.63,77.02 131.57,76.96 131.57,76.77 131.45,76.64 131.19,76.64 131.06,76.77 131.06,77.27 131.34,77.55 131.37,77.55 131.48,77.66 131.48,78.01 131.28,78.2 131.07,78.2 130.75,77.89 130.15,77.89 130.03,77.76 130.03,77.45 129.91,77.33 129.67,77.33 129.55,77.45 129.55,77.52 129.43,77.64 129.19,77.64 129.07,77.52 129.07,77.45 128.95,77.33 128.71,77.33 128.59,77.45 128.59,77.52 128.47,77.64 128.23,77.64 128.11,77.52 128.11,77.45 127.99,77.33 127.75,77.33 127.63,77.45 127.63,77.52 127.51,77.64 127.27,77.64 127.15,77.52 127.15,77.45 127.03,77.33 126.22,77.33 126.06,77.18 125.83,77.18 125.71,77.31 125.71,77.52 125.59,77.64 125.2,77.64 125.03,77.47 125.03,77.31 125.21,77.13 125.21,76.98 125.07,76.84 124.85,76.84 124.68,77.02 124.58,77.02 124.26,76.7 124.26,76.46 124.38,76.33 124.53,76.33 124.66,76.21 124.66,75.94 124.53,75.82 124.09,75.82 123.97,75.69 123.97,75.42 124.09,75.29 124.48,75.29 124.6,75.17 124.6,74.94 124.48,74.81 124.09,74.81 123.97,74.69 123.97,74.45 124.09,74.33 125.22,74.33 125.32,74.24 125.32,73.95 125.22,73.85 124.09,73.85 123.97,73.73 123.97,73.49 124.09,73.37 124.78,73.37 124.91,73.25 124.91,73.05 124.75,72.89 124.28,72.89 124.12,72.74 v4(124.12,72.63) 124.12,71.02 123.45,70.34 121.09,70.34 120.94,70.19 120.94,66.69 121.12,66.51 123.2,66.51 123.97,65.73 123.97,64.15 123.64,63.83 v1(123.05,63.83)
M_MDA33: length 66.8
  TOP w0.099: U1.D16 100.03,59.67 100.37,59.67 100.41,59.71 100.69,59.71 100.72,59.69 101.22,59.69 101.41,59.78 101.47,59.84 101.81,59.84 102.08,59.57 102.64,59.57
  TOP w0.12: v1(123.56,64.31) 123.56,64.36 123.43,64.49 123.09,64.49 123.09,64.5 121.34,64.5 121.34,64.49 121.23,64.49 121.04,64.3 121.02,64.3 119.74,63.03 119.74,62.86 120,62.59 120,62.41 119.85,62.25 119.67,62.25 119.4,62.52 119.23,62.52 119.06,62.35 119.06,62.18 119.99,61.25 119.99,61.11 119.79,60.91 119.65,60.91 118.72,61.84 118.55,61.84 118.38,61.67 118.38,61.5 118.86,61.02 118.86,60.85 118.73,60.73 118.48,60.73 118.04,61.16 117.87,61.16 116.52,59.8 116.39,59.67 102.74,59.67 102.64,59.57
  BOTTOM w0.12: 133.37,78.17 133.46,78.27 133.46,78.45 133.33,78.58 131.56,78.58 131.43,78.7 131.43,79.58 131.31,79.71 130.38,79.71 130.26,79.58 130.26,78.75 130.13,78.62 129.79,78.62 129.66,78.75 129.66,79.62 129.54,79.74 129.3,79.74 129.18,79.62 129.18,79 129.06,78.89 128.82,78.89 128.7,79 128.7,79.62 128.58,79.74 128.34,79.74 128.22,79.62 128.22,79 128.1,78.89 127.86,78.89 127.74,79 127.74,79.62 127.62,79.74 127.38,79.74 127.26,79.62 127.26,79 127.14,78.89 126.16,78.89 125.69,78.42 v4(125.69,78.42) 125.43,78.15 125.15,78.15 123.56,76.56 123.56,71 123.29,70.73 120.65,70.73 120.55,70.63 120.55,66.27 120.69,66.12 123.02,66.12 123.56,65.58 v1(123.56,64.31)
M_MDA34: length 67.6
  TOP w0.099: 102.33,59.91 102.32,59.91 102.2,60.04 101.39,60.04 101.33,59.98 101.08,59.89 100.82,59.89 100.79,59.91 100.33,59.91 100.29,59.88 98.87,59.88 U1.F15
  TOP w0.1: 102.33,59.91 103.59,59.91 103.82,60.14
  TOP w0.12: v1(123.08,64.91) 123.09,64.89 123.25,64.89 123.37,65.02 123.37,65.2 123.25,65.33 122.83,65.33 122.71,65.2 122.71,65.15 122.47,64.91 121.07,64.91 120.86,64.69 120.85,64.69 118.56,62.4 118.43,62.4 v4(117.81,61.78) 116.17,60.14 103.82,60.14
  BOTTOM w0.12: v1(123.08,64.91) 123.08,65.21 122.56,65.72 120.53,65.72 120.13,66.13 120.13,70.54 120.02,70.65 119.64,70.65 119.52,70.52 119.52,70 119.39,69.88 119.11,69.88 118.98,70 118.98,70.75 119.36,71.13 122.96,71.13 123.08,71.25 123.08,71.4 122.96,71.53 120.25,71.53 120.13,71.65 120.13,71.86 120.25,71.98 122.96,71.98 123.08,72.11 123.08,72.44 122.96,72.56 122.88,72.56 122.76,72.69 122.76,72.93 122.88,73.06 122.96,73.06 123.08,73.18 123.08,76.64 126.57,80.13 133.51,80.13 133.72,79.92 133.72,79.17 133.53,78.97 133.37,78.97
M_MDA35: length 66.4
  TOP w0.099: U1.A15 100.99,60.24 102.75,60.24 102.75,60.23
  TOP w0.12: 102.75,60.23 103.06,60.55 115.75,60.55 118.53,63.32 v4(118.69,63.32) 118.69,63.31 119.87,64.49 119.92,64.49 v1(119.98,64.55)
  BOTTOM w0.12: v1(119.98,64.55) 119.87,64.55 119.75,64.67 119.75,65.47 119.62,65.59 119.3,65.59 119.3,65.59 119.02,65.59 118.89,65.72 118.89,65.96 119.01,66.07 119.62,66.07 119.74,66.19 119.74,66.43 119.62,66.55 118.73,66.55 118.6,66.43 118.6,66.39 118.48,66.27 118.33,66.27 118.21,66.39 118.21,66.94 118.3,67.03 119.62,67.03 119.74,67.15 119.74,67.39 119.62,67.51 118.32,67.51 118.19,67.64 118.19,67.87 118.32,67.99 119.62,67.99 119.74,68.11 119.74,68.35 119.62,68.47 117.92,68.47 117.78,68.62 117.78,68.83 117.9,68.95 119.62,68.95 119.74,69.07 119.74,69.31 119.62,69.43 117.46,69.43 117.34,69.31 117.34,68.73 117.21,68.61 117,68.61 116.88,68.73 116.88,69.75 117,69.88 117.58,69.88 117.62,69.92 118.39,69.92 118.52,70.04 118.52,70.33 118.32,70.52 118.32,70.66 120.06,72.39 121.63,72.39 122.63,73.39 122.63,76.74 125.85,79.97 125.85,80.36 126.01,80.52 133.43,80.52 134.16,79.79 U402.A7
M_MDA36: length 66.9
  TOP w0.1: 102.73,61.93 102.69,61.93 102.4,61.64 101.63,61.64 101.61,61.63 101.46,61.48 100.81,61.48 100.78,61.52 100.33,61.52 100.15,61.34 100.09,61.34 U1.D14
  TOP w0.12: 102.73,61.93 104.88,61.93 105.51,62.56 109.38,62.56 111.55,64.73 111.72,64.73 111.84,64.61 111.84,63.82 111.97,63.7 112.25,63.7 112.38,63.82 112.38,65.33 112.5,65.46 112.74,65.46 112.89,65.31 112.89,63.5 113.02,63.38 113.28,63.38 113.41,63.5 113.41,65.23 113.53,65.36 113.81,65.36 113.93,65.23 113.93,64.97 113.94,64.96 113.94,62.62 114.03,62.53 114.33,62.53 114.43,62.63 114.43,65.08 v5(114.77,65.43)
  BOTTOM w0.12: v5(114.77,65.43) 115.01,65.67 115.01,67.64 114.84,67.81 114.84,68.56 115.01,68.74 115.01,69.05 114.84,69.22 114.84,69.53 115.01,69.7 115.01,70 114.84,70.18 114.84,70.48 115.01,70.66 115.01,71.05 115.73,71.77 116.81,71.77 119.64,74.6 119.64,75.04 119.65,75.05 119.65,77.77 123.01,81.13 123.01,83.19 123.36,83.54 134.25,83.54 137.34,80.44 137.34,79.8 137.37,79.78
M_MDA37: length 67.4
  TOP w0.099: U1.F13 98.97,62.11 99.22,62.11 99.33,62.11 100.53,62.12 100.73,62.31 101.29,62.31 101.36,62.24 101.85,62.24 102.29,62.68
  TOP w0.12: v1(110.97,66.22) 110.88,66.22 108.89,64.22 v4(108.89,64.15) 108.35,63.79 106.13,63.79 105.19,63.8 104.07,62.68 102.29,62.68
  BOTTOM w0.12: 137.37,78.17 137.72,77.82 138.31,77.82 138.61,78.12 138.61,78.32 138.82,78.53 139.02,78.53 140.12,79.63 140.12,80.37 139.56,80.93 139.16,80.93 135.37,84.71 122.87,84.71 121.84,83.68 121.84,81.62 119.68,79.46 117.25,79.46 117.03,79.25 115.31,77.55 115.31,76.68 115.82,76.17 115.98,76.17 115.99,76.17 117.2,76.17 117.55,75.83 118.2,75.83 118.45,75.57 118.45,75.08 116.33,72.95 114.92,72.95 114.38,72.42 114.19,72.42 113.66,71.88 113.66,68.91 v1(110.97,66.22)
M_MDA38: length 66.3
  TOP w0.099: 101,61.75 101.44,61.75 101.51,61.82
  TOP w0.1: 101,61.75 100.95,61.79 U1.A13 ; 101.51,61.82 101.53,61.84 102.31,61.84 102.64,62.16 103.63,62.16
  TOP w0.12: v1(112.47,66.22) 111.91,65.52 v4(111.72,65.3) 111.33,65.06 111.29,65.03 109.22,62.96 105.4,62.96 104.61,62.16 103.63,62.16
  BOTTOM w0.12: U402.A2 137.94,79.78 137.94,79.78 137.84,79.78 137.75,79.88 137.75,80.6 134.41,83.93 123.2,83.93 122.62,83.36 122.62,81.3 120,78.67 119.47,78.67 119.46,78.67 117.64,78.67 117.52,78.55 117.52,78.4 117.64,78.28 119.22,78.28 119.34,78.15 119.34,78.02 119.17,77.84 117.47,77.84 117.38,77.75 117.38,77.51 117.47,77.42 119.08,77.42 119.18,77.32 119.18,77.12 119.08,77.02 117.88,77.02 117.77,76.91 117.77,76.74 117.9,76.61 118.53,76.61 118.53,76.6 119.06,76.6 119.25,76.4 119.25,75.21 119.25,75.2 119.25,74.76 116.65,72.17 115.3,72.17 114.44,71.31 114.44,68.91 114.44,68.91 114.44,68.36 114.44,68.35 114.44,68.03 114.32,67.91 113.77,67.91 113.5,67.64 113.5,67.47 113.63,67.35 114.51,67.35 114.62,67.25 114.62,66.97 114.51,66.86 113.07,66.86 112.97,66.75 112.97,66.24 112.84,66.11 112.57,66.11 v1(112.47,66.22)
M_MDA39: length 66.6
  TOP w0.099: U1.C13 100.5,61.8 100.82,62.11 101.08,62.11 101.13,62.06 101.16,62.04 102.19,62.04 102.39,62.23
  TOP w0.12: v1(111.75,66.22) 110.45,64.92 v4(110.38,64.92) 110.38,64.85 108.94,63.4 105.25,63.4 104.24,62.39 102.54,62.39 102.39,62.23
  BOTTOM w0.12: U402.C2 138.16,78.39 138.52,78.74 138.52,79.1 138.7,79.28 138.7,79.49 138.52,79.67 138.52,80.08 138.16,80.44 138.16,80.73 138.09,80.8 138.09,80.97 138.21,81.1 138.21,81.27 138.05,81.44 137.87,81.44 137.75,81.31 137.58,81.31 137.41,81.48 137.41,81.65 137.49,81.73 137.49,81.89 137.31,82.07 137.15,82.07 137.07,81.99 136.9,81.99 136.73,82.16 136.73,82.33 136.81,82.41 136.81,82.57 136.63,82.75 136.47,82.75 136.39,82.67 136.22,82.67 136.05,82.84 136.05,83.01 136.13,83.09 136.13,83.25 135.95,83.43 135.79,83.43 135.71,83.35 135.54,83.35 135.37,83.52 135.37,83.69 135.45,83.77 135.45,83.93 135.27,84.11 135.11,84.11 135.03,84.03 134.87,84.03 134.57,84.32 123.03,84.32 122.23,83.52 122.23,81.46 119.84,79.07 117.42,79.07 117.32,78.97 117.31,78.97 116.77,78.42 116.77,78.22 116.82,78.17 116.99,78 116.99,77.82 116.82,77.66 116.65,77.66 116.4,77.91 116.25,77.91 116.04,77.69 116.04,77.27 115.91,77.14 115.82,77.14 115.71,77.03 115.71,76.84 115.98,76.57 116.39,76.57 116.52,76.69 116.52,77.08 116.64,77.21 116.87,77.21 117,77.08 117,76.65 117.09,76.56 117.37,76.56 117.71,76.22 118.36,76.22 118.38,76.2 118.59,76.2 118.85,75.94 118.85,75.36 118.85,75.36 118.85,74.92 116.49,72.56 115.08,72.56 114.54,72.03 114.36,72.03 114.05,71.72 114.05,68.75 112.57,67.27 112.57,66.87 112.46,66.75 112.06,66.75 111.75,66.44 v1(111.75,66.22)
M_MDA40: length 66.7
  TOP w0.099: 100.01,63.71 100.28,63.71 100.31,63.69 100.79,63.69 100.82,63.71 101.35,63.71 101.39,63.67 101.92,63.67 101.92,63.67
  TOP w0.1: 101.92,63.67 102.86,63.67 ; 100.01,63.71 99.97,63.67 99.62,63.67 U1.E11
  TOP w0.12: 102.86,63.67 103.12,63.67 104.91,65.45 107.63,65.45 112.19,70.02 121.49,70.02 121.61,69.9 121.61,68.02 121.74,67.89 122.08,67.89 122.2,68.02 122.2,69.94 122.29,70.02 122.66,70.02 122.73,69.95 122.73,69.95 122.74,69.94 122.74,67.97 122.86,67.84 123.1,67.84 123.21,67.96 123.22,67.97 123.22,69.94 123.22,69.95 123.33,70.06 123.58,70.06 123.69,69.95 123.7,69.94 123.7,67.99 123.82,67.86 124.05,67.86 124.18,67.99 124.18,69.94 124.18,69.95 124.18,70.85 124.3,70.97 124.52,70.97 124.65,70.85 124.65,67.67 124.77,67.55 125.11,67.55 125.23,67.67 125.23,70.81 125.36,70.94 125.66,70.94 125.78,70.81 125.78,69.82 125.79,67.37 v1(126.29,66.86)
  BOTTOM w0.12: v1(126.29,66.86) 126.29,66.88 125.86,67.31 125.86,67.58 125.84,67.59 125.84,71.77 126.78,72.69 127.09,72.69 127.1,72.69 130.04,72.69 v4(130.8,73.44) 131.03,73.68 132.37,73.68 132.47,73.78 132.67,73.78 133.06,74.17 133.37,74.17
M_MDA41: length 65.8
  TOP w0.099: U1.A11 100.99,63.44 102.83,63.44 102.84,63.43
  TOP w0.12: v1(125.63,66.55) 125.62,66.56 125.1,66.56 124.26,67.41 121.22,67.41 121.1,67.53 121.1,69.5 120.98,69.62 120.74,69.62 120.62,69.5 120.62,67.53 120.5,67.41 120.26,67.41 120.14,67.53 120.14,69.5 120.02,69.62 119.78,69.62 119.66,69.5 119.66,67.53 119.54,67.41 119.3,67.41 119.18,67.53 119.18,69.5 119.06,69.62 118.82,69.62 118.7,69.5 118.7,67.53 118.58,67.41 118.34,67.41 118.22,67.53 118.22,69.5 118.1,69.62 117.86,69.62 117.74,69.5 117.74,67.53 117.62,67.41 117.38,67.41 117.26,67.53 117.26,69.5 117.14,69.62 116.88,69.62 116.76,69.5 116.76,68.56 116.64,68.44 116.41,68.44 116.28,68.56 116.28,69.5 116.28,69.5 116.16,69.62 112.35,69.62 107.71,64.98 104.99,64.98 103.45,63.44 102.85,63.44 102.84,63.43
  BOTTOM w0.12: v1(125.63,66.55) 125.63,66.7 125.47,66.86 125.47,67.42 125.45,67.44 125.45,71.92 126.5,72.97 126.5,74.65 126.98,75.14 129.46,75.14 v4(129.73,74.86) 130.03,74.56 133.45,74.56 133.81,74.92 133.81,75.42 U402.F7
M_MDA42: length 66.2
  TOP w0.099: 102.33,63.22 101.83,63.22 101.81,63.24 101.29,63.24 101.2,63.15 101.15,63.11 101.12,63.09 101.11,63.09 100.82,63.09 100.79,63.12 100.77,63.12 ; U1.C11 100.15,63.31 100.35,63.12
  TOP w0.1: 102.33,63.22 102.94,63.22 ; 100.35,63.12 100.77,63.12
  TOP w0.12: 102.94,63.22 103.78,63.22 105.15,64.58 107.88,64.58 110.31,67.02 111.35,67.02 111.47,67.14 111.47,67.69 111.59,67.82 111.82,67.82 111.95,67.69 111.95,67.14 112.07,67.02 112.31,67.02 112.43,67.14 112.43,68.75 112.56,68.88 112.79,68.88 112.79,68.88 112.91,68.76 112.91,68.63 112.91,68.63 112.91,67.14 113.03,67.02 113.27,67.02 113.39,67.14 113.39,68.78 113.52,68.91 113.75,68.91 113.88,68.78 113.88,68.78 113.88,67.14 114,67.02 114.23,67.02 114.35,67.14 114.35,68.81 114.46,68.92 114.73,68.92 114.84,68.81 114.84,68.81 114.84,67.14 114.96,67.02 115.19,67.02 115.31,67.14 115.31,68.8 115.43,68.92 115.68,68.92 115.8,68.8 115.8,68.8 115.8,67.14 115.92,67.02 116.15,67.02 116.27,67.14 116.27,67.69 116.39,67.81 116.62,67.81 116.75,67.69 116.75,67.14 116.87,67.02 124.09,67.02 124.99,66.12 v1(125.06,66.12)
  BOTTOM w0.12: 133.37,75.78 133.15,75.78 132.79,75.42 131.63,75.42 131.17,74.96 130.6,74.96 130.03,75.53 126.83,75.53 126.11,74.81 126.11,73.13 125.06,72.09 125.06,70.08 124.93,69.95 124.49,69.95 124.37,69.83 124.37,69.43 124.49,69.31 124.93,69.31 125.06,69.18 125.06,68.69 124.93,68.56 124.37,68.56 124.37,68.57 123.66,68.57 123.53,68.44 123.53,68.21 123.66,68.08 124.93,68.08 125.06,67.96 125.06,67.73 124.93,67.61 124.37,67.61 124.37,67.61 124.09,67.61 123.97,67.48 123.97,67.21 v4(124.44,66.74) v1(125.06,66.12)
